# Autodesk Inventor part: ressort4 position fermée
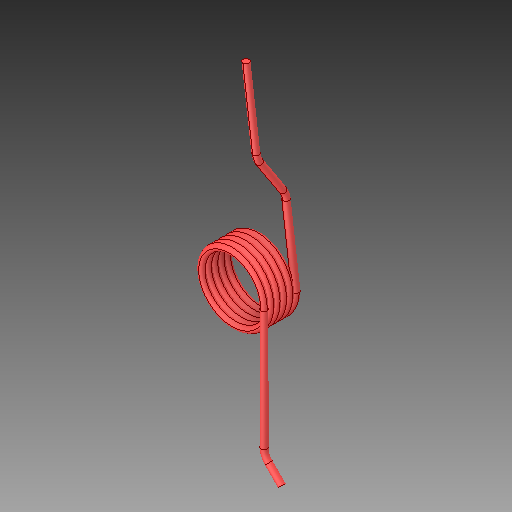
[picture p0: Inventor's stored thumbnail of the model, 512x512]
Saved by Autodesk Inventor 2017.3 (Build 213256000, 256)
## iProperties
Created: 2007-12
Part Number: ressort4 position fermée
Material: Générique
Document SubType Name: Modeling
Designer: ficho
Density: 1 g/cm^3
Appearance: Par défaut
Author: ficho
Sending System: SolidWorks 2009
Last Author: christophe
Last Saved: 2011-02-10
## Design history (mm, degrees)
feature "Balayage14"
node "Solide1"
